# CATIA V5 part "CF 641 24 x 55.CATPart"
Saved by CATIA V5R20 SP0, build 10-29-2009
Part number: CF 641 24 x 55
Definition: NONE
Nomenclature: CF 641 24 x 55
Source: Unknown
Description: CF 641 24 x 55
Bounding box of the stored display mesh (mm): x -32 to 23, y -22 to 22, z -22 to 22
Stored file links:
  C:\Users\Utente\Desktop\IO LAVORO\3D X SITO CF\X SITO\CF 641\CF 641 24 x 55.CATPart
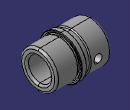
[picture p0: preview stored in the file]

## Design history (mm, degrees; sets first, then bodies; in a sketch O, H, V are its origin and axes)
Body1 "CF 641 24 x 55" (main body)
  Solid1: solid without history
